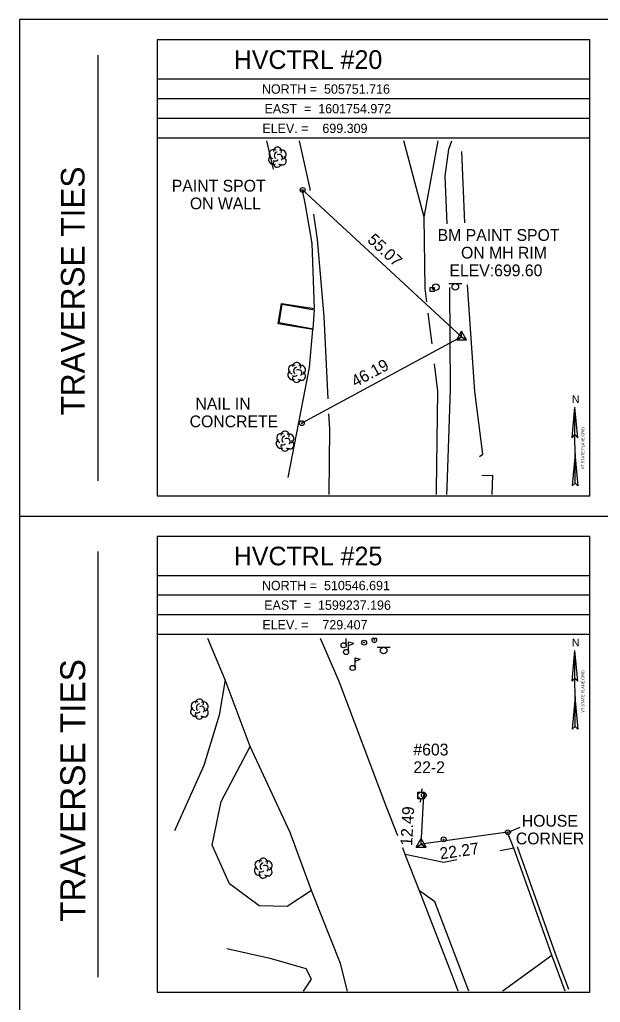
# Model space of a CAD drawing. Extents: x 1598730 to 1599370, y 501440 to 502728.
# Drawn here: x 1598729.5 to 1598877.2, y 501610.1 to 501860.2 of the extents above; entities that cross this region are included whole.
import ezdxf

# ---------------------------------------------------------------- set-up
doc = ezdxf.new("R2010")
doc.units = 0
for name, color, linetype in [('C_C', 7, 'Continuous'), ('CBP', 7, 'Continuous'), ('CPBM', 7, 'Continuous'), ('CPSM', 7, 'Continuous'), ('Default', 7, 'Continuous'), ('LBC', 7, 'Continuous'), ('LBF', 7, 'Continuous'), ('LMB', 7, 'Continuous'), ('LPST', 7, 'Continuous'), ('LTD', 7, 'Continuous'), ('LW', 7, 'Continuous'), ('NBL1', 7, 'Continuous'), ('NBL2', 7, 'Continuous'), ('NNA_P', 7, 'Continuous'), ('PET', 7, 'Continuous'), ('PSP', 7, 'Continuous'), ('RDG', 7, 'Continuous'), ('RGR', 7, 'Continuous'), ('SSGN', 7, 'Continuous'), ('U_C', 7, 'Continuous'), ('UP', 7, 'Continuous'), ('UPGW', 7, 'Continuous'), ('UTMH', 7, 'Continuous')]:
    doc.layers.add(name, color=color, linetype=linetype)

msp = doc.modelspace()

# ---------------------------------------------------------------- linework, layer by layer
at = {"layer": 'CBP'}
for centre, radius in [((1598801.51, 501816.87), 0.625), ((1598801.51, 501816.87), 0.0833), ((1598801.3, 501757.52), 0.625), ((1598801.3, 501757.52), 0.0833), ((1598832.34, 501662.83), 0.625), ((1598832.34, 501662.83), 0.0833), ((1598853.72, 501653.41), 0.625), ((1598853.72, 501653.41), 0.0833)]:
    msp.add_circle(centre, radius, dxfattribs=at)
at = {"layer": 'CPBM'}
for p, q in [((1598833.93, 501791.07), (1598833.93, 501792.07)), ((1598833.93, 501792.07), (1598834.93, 501792.07)), ((1598834.93, 501791.07), (1598833.93, 501791.07)), ((1598834.43, 501791.57), (1598834.43, 501791.57)), ((1598834.43, 501791.57), (1598834.43, 501791.57)), ((1598834.93, 501792.07), (1598834.93, 501791.07))]:
    msp.add_line(p, q, dxfattribs=at)
at = {"layer": 'CPSM'}
for p, q in [((1598840.7, 501778.75), (1598841.95, 501780.92)), ((1598843.2, 501778.75), (1598841.95, 501780.92)), ((1598841.95, 501779.47), (1598841.95, 501780.92)), ((1598840.7, 501778.75), (1598841.95, 501779.47)), ((1598840.7, 501778.75), (1598843.2, 501778.75)), ((1598841.95, 501779.47), (1598841.95, 501779.47)), ((1598841.95, 501779.47), (1598843.2, 501778.75)), ((1598830.41, 501649.64), (1598831.66, 501651.81)), ((1598830.41, 501649.64), (1598831.66, 501650.37)), ((1598832.91, 501649.64), (1598831.66, 501651.81)), ((1598831.66, 501650.37), (1598831.66, 501651.81)), ((1598831.66, 501650.37), (1598831.66, 501650.37)), ((1598831.66, 501650.37), (1598832.91, 501649.64)), ((1598830.41, 501649.64), (1598832.91, 501649.64))]:
    msp.add_line(p, q, dxfattribs=at)
at = {"layer": 'Default'}
for p, q in [((1598801.51, 501816.87), (1598841.95, 501779.47)), ((1598841.95, 501779.47), (1598801.3, 501757.52)), ((1598831.66, 501650.37), (1598832.34, 501662.83)), ((1598853.72, 501653.41), (1598831.66, 501650.37))]:
    msp.add_line(p, q, dxfattribs=at)
at = {"layer": 'LBC'}
msp.add_line((1598869.23, 501613.36), (1598865.87, 501622.48), dxfattribs=at)
for points in [[(1598864.93, 501622.14), (1598855.2, 501649.38), (1598853.65, 501653.33), (1598856.81, 501654.74)], [(1598865.87, 501622.47), (1598856.13, 501649.73)], [(1598868.29, 501613.01), (1598864.93, 501622.14)]]:
    msp.add_lwpolyline(points, dxfattribs=at)
at = {"layer": 'LBF'}
for points in [[(1598804.17, 501781.44), (1598795.54, 501783.03), (1598796.3, 501787.79), (1598804.52, 501786.4)], [(1598804.17, 501781.44), (1598804.52, 501786.4)]]:
    msp.add_lwpolyline(points, dxfattribs=at)
at = {"layer": 'LMB'}
for p, q in [((1598812.59, 501701.01), (1598812.59, 501702.68)), ((1598811.94, 501701), (1598811.94, 501701)), ((1598813.21, 501699.29), (1598813.21, 501701.89)), ((1598813.21, 501701.88), (1598814.5, 501701.5)), ((1598813.21, 501700.98), (1598814.5, 501701.49)), ((1598812.56, 501699.28), (1598812.56, 501699.28)), ((1598814.88, 501697.83), (1598816.17, 501697.45)), ((1598814.88, 501695.24), (1598814.88, 501697.83)), ((1598814.88, 501696.93), (1598816.16, 501697.44)), ((1598814.23, 501695.23), (1598814.23, 501695.23))]:
    msp.add_line(p, q, dxfattribs=at)
for centre in [(1598811.94, 501701), (1598812.56, 501699.28), (1598814.23, 501695.23)]:
    msp.add_circle(centre, 0.656, dxfattribs=at)
at = {"layer": 'LPST'}
msp.add_line((1598820.31, 501702.68), (1598819.22, 501702.68), dxfattribs=at)
for centre, radius in [((1598817.16, 501701.67), 0.625), ((1598819.77, 501702.37), 0.0833), ((1598817.16, 501701.67), 0.0833)]:
    msp.add_circle(centre, radius, dxfattribs=at)
msp.add_arc((1598819.77, 501702.37), 0.625, 150.0855, 29.9145, dxfattribs=at)
at = {"layer": 'LTD'}
for p, q in [((1598795.07, 501825.26), (1598795.07, 501825.26)), ((1598795.07, 501825.26), (1598795.07, 501825.26)), ((1598799.97, 501770.48), (1598799.97, 501770.48)), ((1598799.97, 501770.48), (1598799.97, 501770.48)), ((1598797.01, 501753), (1598797.01, 501753)), ((1598797.01, 501753), (1598797.01, 501753)), ((1598775.24, 501684.8), (1598775.24, 501684.8)), ((1598775.24, 501684.8), (1598775.24, 501684.8)), ((1598791.47, 501644.33), (1598791.47, 501644.33)), ((1598791.47, 501644.33), (1598791.47, 501644.33))]:
    msp.add_line(p, q, dxfattribs=at)
for centre in [(1598795.12, 501826.7), (1598800.02, 501771.91), (1598797.05, 501754.43), (1598775.29, 501686.24), (1598791.52, 501645.76)]:
    msp.add_arc(centre, 1.05, 335.5272, 180.9563, dxfattribs=at)
for centre, major_axis, ratio, start_param, end_param in [((1598794.28, 501825.93), (1.21, -0.51), 0.895232, 1.570796, 4.712389), ((1598793.99, 501824.55), (0.58, -1.04), 0.959034, 3.141593, 6.283185), ((1598794.86, 501825.72), (-0.208, -0.792), 0.645439, 3.141593, 6.283185), ((1598795.57, 501825.1), (-0.5, 0.667), 0.989748, 3.141593, 6.283185), ((1598796.07, 501824.43), (-1.09, 0.79), 0.841452, 1.570796, 4.712389), ((1598796.11, 501825.85), (-1.14, -0.48), 0.949671, 1.570796, 4.712389), ((1598795.07, 501823.76), (0.26, 1.06), 0.942809, 1.570796, 4.712389), ((1598794.61, 501824.51), (-0.625, -0.083), 0.423636, 0, 3.141593), ((1598799.18, 501771.14), (1.21, -0.51), 0.895232, 1.570796, 4.712389), ((1598801.01, 501771.06), (-1.14, -0.48), 0.949671, 1.570796, 4.712389), ((1598798.89, 501769.77), (0.58, -1.04), 0.959034, 3.141593, 6.283185), ((1598799.51, 501769.73), (-0.625, -0.083), 0.423636, 0, 3.141593), ((1598799.76, 501770.94), (-0.208, -0.792), 0.645439, 3.141593, 6.283185), ((1598800.47, 501770.31), (-0.5, 0.667), 0.989748, 3.141593, 6.283185), ((1598800.97, 501769.64), (-1.09, 0.79), 0.841452, 1.570796, 4.712389), ((1598799.97, 501768.98), (0.26, 1.06), 0.942809, 1.570796, 4.712389), ((1598796.21, 501753.67), (1.21, -0.51), 0.895232, 1.570796, 4.712389), ((1598798.05, 501753.58), (-1.14, -0.48), 0.949671, 1.570796, 4.712389), ((1598795.92, 501752.29), (0.58, -1.04), 0.959034, 3.141593, 6.283185), ((1598796.55, 501752.25), (-0.625, -0.083), 0.423636, 0, 3.141593), ((1598796.8, 501753.46), (-0.208, -0.792), 0.645439, 3.141593, 6.283185), ((1598797.51, 501752.83), (-0.5, 0.667), 0.989748, 3.141593, 6.283185), ((1598798.01, 501752.17), (-1.09, 0.79), 0.841452, 1.570796, 4.712389), ((1598797.01, 501751.5), (0.26, 1.06), 0.942809, 1.570796, 4.712389), ((1598774.16, 501684.09), (0.58, -1.04), 0.959034, 3.141593, 6.283185), ((1598774.45, 501685.47), (1.21, -0.51), 0.895232, 1.570796, 4.712389), ((1598775.03, 501685.26), (-0.208, -0.792), 0.645439, 3.141593, 6.283185), ((1598775.74, 501684.64), (-0.5, 0.667), 0.989748, 3.141593, 6.283185), ((1598776.24, 501683.97), (-1.09, 0.79), 0.841452, 1.570796, 4.712389), ((1598776.28, 501685.39), (-1.14, -0.48), 0.949671, 1.570796, 4.712389), ((1598775.24, 501683.3), (0.26, 1.06), 0.942809, 1.570796, 4.712389), ((1598774.78, 501684.05), (-0.625, -0.083), 0.423636, 0, 3.141593), ((1598790.39, 501643.62), (0.58, -1.04), 0.959034, 3.141593, 6.283185), ((1598790.68, 501645), (1.21, -0.51), 0.895232, 1.570796, 4.712389), ((1598791.26, 501644.79), (-0.208, -0.792), 0.645439, 3.141593, 6.283185), ((1598791.97, 501644.16), (-0.5, 0.667), 0.989748, 3.141593, 6.283185), ((1598792.51, 501644.91), (-1.14, -0.48), 0.949671, 1.570796, 4.712389), ((1598791.47, 501642.83), (0.26, 1.06), 0.942809, 1.570796, 4.712389), ((1598791.01, 501643.58), (-0.625, -0.083), 0.423636, 0, 3.141593), ((1598792.47, 501643.5), (-1.09, 0.79), 0.841452, 1.570796, 4.712389)]:
    msp.add_ellipse(centre, major_axis=major_axis, ratio=ratio, start_param=start_param, end_param=end_param, dxfattribs=at)
at = {"layer": 'LW'}
for points in [[(1598794.06, 501822.13), (1598792.39, 501829.4)], [(1598842.79, 501808.51), (1598842.02, 501826.69)], [(1598797.85, 501743.69), (1598803.25, 501771.71), (1598804.11, 501781.34), (1598795.32, 501782.82), (1598796.11, 501787.94), (1598804.52, 501786.67), (1598803.9, 501803.24), (1598802.28, 501813.06), (1598801.46, 501816.79), (1598800.76, 501816.73)], [(1598846.49, 501749.02), (1598847.38, 501749.65), (1598845.27, 501765.6), (1598843.45, 501792.74)], [(1598849.76, 501739.39), (1598849.85, 501744.22), (1598847.13, 501744.15)]]:
    msp.add_lwpolyline(points, dxfattribs=at)
at = {"layer": 'NBL1'}
msp.add_lwpolyline([(1598729.53, 501440.21), (1599369.53, 501440.21), (1599369.53, 501860.21), (1598729.53, 501860.21)], close=True, dxfattribs=at)
at = {"layer": 'NBL2'}
for p, q in [((1598749.53, 501742.88), (1598749.53, 501851.21)), ((1598874.53, 501845.04), (1598764.53, 501845.04)), ((1598874.53, 501840.04), (1598764.53, 501840.04)), ((1598874.53, 501835.04), (1598764.53, 501835.04)), ((1598874.53, 501830.04), (1598764.53, 501830.04)), ((1598729.53, 501733.88), (1599369.53, 501733.88)), ((1598749.53, 501616.54), (1598749.53, 501724.88)), ((1598874.53, 501718.71), (1598764.53, 501718.71)), ((1598874.53, 501713.71), (1598764.53, 501713.71)), ((1598874.53, 501708.71), (1598764.53, 501708.71)), ((1598874.53, 501703.71), (1598764.53, 501703.71))]:
    msp.add_line(p, q, dxfattribs=at)
for points in [[(1598764.53, 501739.04), (1598874.53, 501739.04), (1598874.53, 501855.04), (1598764.53, 501855.04)], [(1598764.53, 501612.71), (1598874.53, 501612.71), (1598874.53, 501728.71), (1598764.53, 501728.71)]]:
    msp.add_lwpolyline(points, close=True, dxfattribs=at)
at = {"layer": 'NNA_P'}
for p, q in [((1598870.09, 501753.83), (1598870.78, 501761.62)), ((1598870.79, 501742.25), (1598870.78, 501761.62)), ((1598871.48, 501753.83), (1598870.78, 501761.62)), ((1598870.09, 501753.83), (1598870.78, 501754.6)), ((1598871.48, 501753.83), (1598870.78, 501754.6)), ((1598870.79, 501749.77), (1598870.07, 501741.61)), ((1598870.78, 501749.77), (1598871.51, 501741.61)), ((1598870.79, 501742.25), (1598870.07, 501741.61)), ((1598870.79, 501742.25), (1598871.51, 501741.61)), ((1598870.09, 501691.89), (1598870.78, 501699.68)), ((1598870.79, 501680.31), (1598870.78, 501699.68)), ((1598871.48, 501691.89), (1598870.78, 501699.68)), ((1598870.09, 501691.89), (1598870.78, 501692.66)), ((1598871.48, 501691.89), (1598870.78, 501692.66)), ((1598870.79, 501687.84), (1598870.07, 501679.67)), ((1598870.78, 501687.84), (1598871.51, 501679.67)), ((1598870.79, 501680.31), (1598870.07, 501679.67)), ((1598870.79, 501680.31), (1598871.51, 501679.67))]:
    msp.add_line(p, q, dxfattribs=at)
at = {"layer": 'PET'}
for points in [[(1598803.45, 501816.74), (1598803.39, 501817.16), (1598800.71, 501829.4)], [(1598833.09, 501788.42), (1598832.67, 501791.78), (1598832.43, 501809.92), (1598827.24, 501829.4)], [(1598808.03, 501763.74), (1598807.03, 501784.64), (1598805.31, 501804.3), (1598804.35, 501810.73)], [(1598834.43, 501777.68), (1598833.46, 501785.48)], [(1598835.55, 501739.39), (1598835.59, 501740.47), (1598835.93, 501765.68), (1598835.06, 501772.59)], [(1598808.22, 501739.39), (1598808.39, 501756.1), (1598808.21, 501759.89)], [(1598812.94, 501613.01), (1598811.16, 501620.05), (1598803.79, 501638.56), (1598798.32, 501653.32), (1598788.16, 501675.25), (1598781.83, 501692.21), (1598777.39, 501702.68)], [(1598825.75, 501652.51), (1598822.72, 501660.09), (1598810.84, 501691.74), (1598806.08, 501702.68)], [(1598841.07, 501613.01), (1598839.98, 501615.94), (1598831.24, 501638.48), (1598827.63, 501647.79), (1598826.98, 501649.41)]]:
    msp.add_lwpolyline(points, dxfattribs=at)
at = {"layer": 'PSP'}
msp.add_lwpolyline([(1598843.75, 501613.01), (1598842.47, 501616.52), (1598835.15, 501635.73), (1598831.24, 501638.48)], dxfattribs=at)
at = {"layer": 'RDG'}
for points in [[(1598832.43, 501809.92), (1598835.99, 501829.4)], [(1598781.83, 501692.21), (1598780.28, 501683.24), (1598776.34, 501670.37), (1598768.94, 501653.8)], [(1598803.79, 501638.56), (1598797.57, 501634.53), (1598790.44, 501634.66), (1598782.9, 501640.25), (1598778.53, 501650.12), (1598780.75, 501661.24), (1598788.16, 501675.25)], [(1598840.71, 501646.4), (1598837.44, 501645.73), (1598827.63, 501647.79)], [(1598855.2, 501649.38), (1598851.78, 501648.68)], [(1598801.7, 501613.01), (1598803.77, 501616.05), (1598802.44, 501618.65), (1598793.6, 501621.24), (1598782.21, 501623.73)], [(1598852.54, 501613.01), (1598852.5, 501613.17), (1598864.93, 501622.14)]]:
    msp.add_lwpolyline(points, dxfattribs=at)
at = {"layer": 'RGR'}
for points in [[(1598838.27, 501808.23), (1598837.78, 501820.4), (1598838.66, 501827.23), (1598839.48, 501829.4)], [(1598838.2, 501739.39), (1598838.31, 501741.15), (1598839.16, 501766.12), (1598838.93, 501792.02)]]:
    msp.add_lwpolyline(points, dxfattribs=at)
at = {"layer": 'SSGN'}
for p, q in [((1598838.7, 501793.08), (1598842.04, 501793.08)), ((1598840.35, 501792.24), (1598840.35, 501792.24)), ((1598820.48, 501700.52), (1598823.81, 501700.52)), ((1598822.12, 501699.69), (1598822.12, 501699.69))]:
    msp.add_line(p, q, dxfattribs=at)
for centre in [(1598840.35, 501792.24), (1598822.12, 501699.69)]:
    msp.add_circle(centre, 0.833, dxfattribs=at)
at = {"layer": 'UP'}
for p, q in [((1598830.82, 501661.94), (1598830.82, 501663.61)), ((1598830.82, 501663.61), (1598832.48, 501663.61)), ((1598831.9, 501664.44), (1598831.65, 501663.61)), ((1598831.65, 501662.78), (1598831.65, 501662.78)), ((1598832.48, 501663.61), (1598832.48, 501661.94)), ((1598832.48, 501661.94), (1598830.82, 501661.94)), ((1598831.4, 501661.11), (1598831.65, 501661.94))]:
    msp.add_line(p, q, dxfattribs=at)
msp.add_circle((1598831.65, 501662.78), 0.833, dxfattribs=at)
at = {"layer": 'UPGW'}
for radius in [0.625, 0.0833]:
    msp.add_circle((1598837.37, 501651.6), radius, dxfattribs=at)
at = {"layer": 'UTMH'}
for p, q in [((1598835.39, 501792.15), (1598835.39, 501792.15)), ((1598836.22, 501792.15), (1598836.22, 501792.15))]:
    msp.add_line(p, q, dxfattribs=at)
msp.add_circle((1598835.39, 501792.15), 0.833, dxfattribs=at)

# ---------------------------------------------------------------- texts
at = {"layer": 'C_C'}
for s, p in [('PAINT SPOT', (1598768.24, 501816.45)), ('ON WALL', (1598772.84, 501811.95)), ('BM PAINT SPOT', (1598835.86, 501803.9)), ('ON MH RIM', (1598841.8, 501799.4)), ('ELEV:699.60', (1598838.85, 501794.9)), ('NAIL IN', (1598774.25, 501760.98)), ('CONCRETE', (1598772.77, 501756.48)), ('HOUSE', (1598857.25, 501654.83)), ('CORNER', (1598855.75, 501650.33))]:
    msp.add_text(s, height=3, dxfattribs=at).set_placement(p)
at = {"layer": 'Default'}
for s, rotation, p in [('55.07', 317.2435, (1598817.76, 501803.88)), ('46.19', 28.3704, (1598814.92, 501766.59)), ('12.49', 86.8665, (1598829.35, 501649.89)), ('22.27', 7.859, (1598836.58, 501646.5))]:
    msp.add_text(s, height=3, rotation=rotation, dxfattribs=at).set_placement(p)
at = {"layer": 'NBL2'}
for s, height, p in [('     HVCTRL #20    ', 4.75, (1598775.18, 501847.67)), ('NORTH =  505751.716 ', 2.375, (1598791.15, 501841.36)), ('EAST  =  1601754.972', 2.375, (1598791.81, 501836.36)), ('ELEV. =    699.309  ', 2.375, (1598791.26, 501831.36)), ('     HVCTRL #25    ', 4.75, (1598775.18, 501721.33)), ('NORTH =  510546.691 ', 2.375, (1598791.15, 501715.02)), ('EAST  =  1599237.196', 2.375, (1598791.74, 501710.02)), ('ELEV. =    729.407  ', 2.375, (1598791.26, 501705.02))]:
    msp.add_text(s, height=height, dxfattribs=at).set_placement(p)
for height, p in [(6, (1598746.03, 501759.51)), (6.3332, (1598746.2, 501630.64))]:
    msp.add_text('TRAVERSE TIES', height=height, rotation=90, dxfattribs=at).set_placement(p)
at = {"layer": 'NNA_P'}
for p in [(1598870.02, 501762.63), (1598870.02, 501700.7)]:
    msp.add_text('N', height=1.97, dxfattribs=at).set_placement(p)
for p in [(1598873.14, 501745.81), (1598873.14, 501683.87)]:
    msp.add_text('VT STATE PLANE GRID', height=0.7, rotation=90.0204, dxfattribs=at).set_placement(p)
at = {"layer": 'U_C'}
for s, p in [('#603', (1598829.68, 501672.96)), ('22-2', (1598829.68, 501668.46))]:
    msp.add_text(s, height=3, dxfattribs=at).set_placement(p)

doc.saveas('drawing.dxf')
